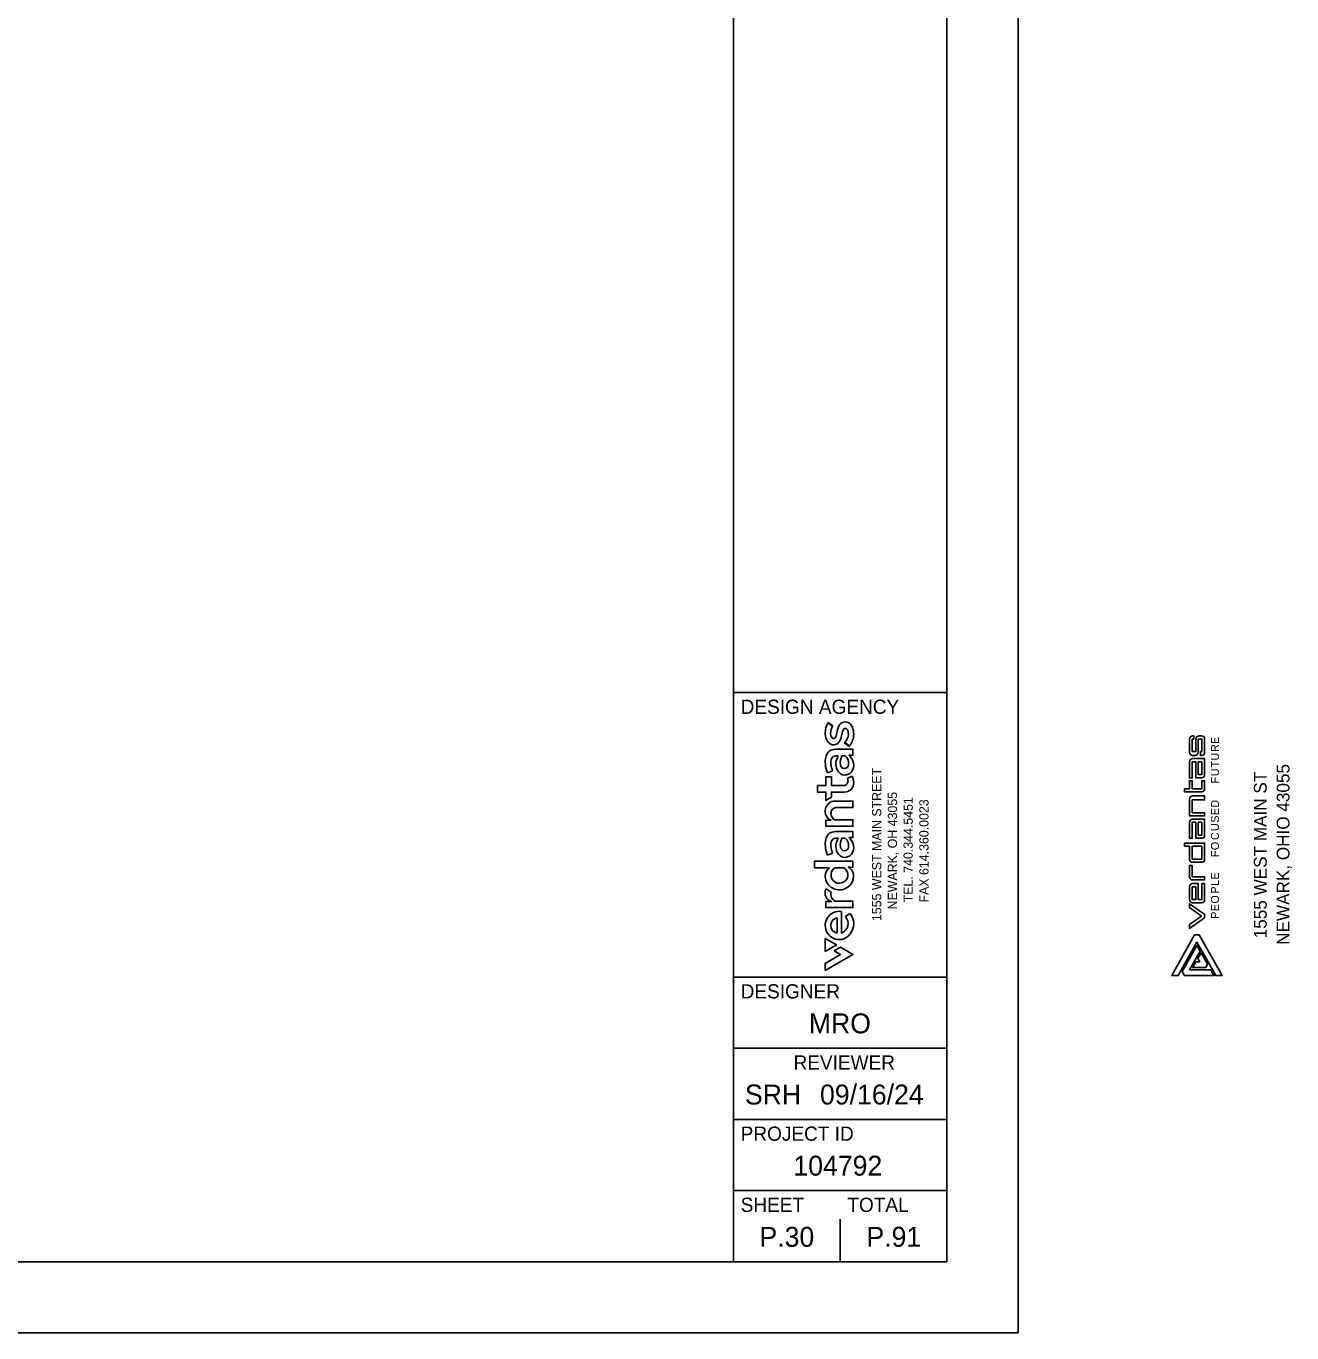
# Model space of a CAD drawing. Extents: x 0 to 35.9, y 0 to 22.
# Drawn here: x 27.03 to 35.93, y 0 to 9.18 of the extents above; entities that cross this region are included whole.
import ezdxf

# ---------------------------------------------------------------- set-up
doc = ezdxf.new("R2010")
doc.units = 0
for name, color, linetype in [('CS-ANNO-TTLB-LOGO', 7, 'Continuous'), ('Default', 7, 'Continuous'), ('SH_Border', 7, 'Continuous'), ('SH_Cut_Line', 7, 'Continuous'), ('SH_Data', 7, 'Continuous'), ('SH_Text', 7, 'Continuous')]:
    doc.layers.add(name, color=color, linetype=linetype)

msp = doc.modelspace()

# ---------------------------------------------------------------- linework, layer by layer
at = {"layer": 'CS-ANNO-TTLB-LOGO'}
for p, q in [((35.205, 4.1732), (35.205, 4.0804)), ((35.2359, 4.1957), (35.2275, 4.1957)), ((35.2893, 4.1957), (35.2725, 4.1957)), ((35.3118, 4.0804), (35.3118, 4.1732)), ((35.2275, 4.0579), (35.2443, 4.0579)), ((35.205, 3.9004), (35.205, 4.0129)), ((35.205, 3.4756), (35.205, 3.5881)), ((35.2275, 3.3069), (35.2893, 3.3069)), ((35.205, 3.1353), (35.205, 3.0453)), ((35.3118, 3.0453), (35.3118, 3.1578)), ((35.2275, 3.0228), (35.2893, 3.0228))]:
    msp.add_line(p, q, dxfattribs=at)
for points in [[(35.25, 4.1732), (35.25, 4.086), (35.2247, 4.086), (35.2247, 4.1732), (35.2359, 4.1732), (35.2359, 4.1957)], [(35.2668, 4.0804), (35.2668, 4.1732), (35.2922, 4.1732), (35.2922, 4.086), (35.2837, 4.086), (35.2837, 4.0579), (35.2893, 4.0579)], [(35.2893, 3.9004), (35.25, 3.9004), (35.25, 4.0129), (35.2247, 4.0129), (35.2247, 3.9004), (35.205, 3.9004)], [(35.2275, 4.0354), (35.3118, 4.0354), (35.3118, 3.9229)], [(35.1703, 3.8244), (35.205, 3.8244), (35.205, 3.8806), (35.2247, 3.8806), (35.2247, 3.8244), (35.2922, 3.8244), (35.2922, 3.8806), (35.3118, 3.8806), (35.3118, 3.8244)], [(35.2893, 3.8019), (35.1703, 3.8019), (35.1703, 3.8244)], [(35.3118, 3.7456), (35.3118, 3.7737), (35.2275, 3.7737)], [(35.205, 3.7512), (35.205, 3.6331), (35.3118, 3.6331), (35.3118, 3.6556), (35.2247, 3.6556), (35.2247, 3.7456), (35.3118, 3.7456)], [(35.2893, 3.4756), (35.25, 3.4756), (35.25, 3.5881), (35.2247, 3.5881), (35.2247, 3.4756), (35.205, 3.4756)], [(35.2275, 3.6106), (35.3118, 3.6106), (35.3118, 3.4981)], [(35.1703, 3.4419), (35.1703, 3.4194), (35.205, 3.4194), (35.205, 3.3294)], [(35.3118, 3.3294), (35.3118, 3.4419), (35.1703, 3.4419)], [(35.3118, 3.2056), (35.2247, 3.2056), (35.2247, 3.2844), (35.205, 3.2844), (35.205, 3.2056)], [(35.2275, 3.1831), (35.3118, 3.1831), (35.3118, 3.2056)], [(35.3118, 3.1578), (35.2922, 3.1578), (35.2922, 3.0453), (35.2668, 3.0453), (35.2668, 3.1578), (35.2275, 3.1578)]]:
    msp.add_lwpolyline(points, dxfattribs=at)
for points in [[(35.2668, 4.0129), (35.2922, 4.0129), (35.2922, 3.9229), (35.2668, 3.9229)], [(35.2668, 3.5881), (35.2922, 3.5881), (35.2922, 3.4981), (35.2668, 3.4981)], [(35.2247, 3.4194), (35.2247, 3.3294), (35.2922, 3.3294), (35.2922, 3.4194)], [(35.25, 3.1353), (35.2247, 3.1353), (35.2247, 3.0453), (35.25, 3.0453)], [(35.2894, 2.929), (35.205, 2.8699), (35.205, 2.8424), (35.3118, 2.9173), (35.3123, 2.9405), (35.2054, 3.0153), (35.205, 2.9882)]]:
    msp.add_lwpolyline(points, close=True, dxfattribs=at)
for centre, start, end in [((35.2275, 4.1732), 90, 180), ((35.2725, 4.1732), 90, 180), ((35.2893, 4.1732), 360, 90), ((35.2275, 4.0804), 180, 270), ((35.2443, 4.0804), 270, 0), ((35.2893, 4.0804), 270, 0), ((35.2275, 4.0129), 90, 180), ((35.2893, 3.9229), 270, 360), ((35.2275, 3.7512), 90, 180), ((35.2893, 3.8244), 270, 360), ((35.2275, 3.5881), 90, 180), ((35.2893, 3.4981), 270, 360), ((35.2275, 3.3294), 180, 270), ((35.2893, 3.3294), 270, 0), ((35.2275, 3.2056), 180, 270), ((35.2275, 3.1353), 90, 180), ((35.2275, 3.0453), 180, 270), ((35.2893, 3.0453), 270, 0)]:
    msp.add_arc(centre, 0.0225, start, end, dxfattribs=at)
at = {"layer": 'Default'}
for p, q in [((35.205, 4.1732), (35.205, 4.0804)), ((35.2893, 4.1957), (35.2725, 4.1957)), ((35.3118, 4.0804), (35.3118, 4.1732)), ((35.2275, 4.0579), (35.2443, 4.0579)), ((35.2275, 3.3069), (35.2893, 3.3069)), ((35.205, 3.1353), (35.205, 3.0453)), ((35.2275, 3.0228), (35.2893, 3.0228)), ((35.1545, 2.5389), (35.2578, 2.7221)), ((35.2804, 2.682), (35.2062, 2.5505)), ((35.2578, 2.7221), (35.2804, 2.682)), ((35.1701, 2.5112), (35.1545, 2.5389)), ((35.3768, 2.5112), (35.1701, 2.5112)), ((35.2062, 2.5505), (35.3545, 2.5505)), ((35.3545, 2.5505), (35.3768, 2.5112))]:
    msp.add_line(p, q, dxfattribs=at)
for points in [[(35.25, 4.1732), (35.25, 4.086), (35.2247, 4.086), (35.2247, 4.1732), (35.2359, 4.1732), (35.2359, 4.1957), (35.2275, 4.1957)], [(35.2668, 4.0804), (35.2668, 4.1732), (35.2922, 4.1732), (35.2922, 4.086), (35.2837, 4.086), (35.2837, 4.0579), (35.2893, 4.0579)], [(35.205, 4.0129), (35.205, 3.9004), (35.2247, 3.9004), (35.2247, 4.0129), (35.25, 4.0129), (35.25, 3.9004), (35.2893, 3.9004)], [(35.3118, 3.9229), (35.3118, 4.0354), (35.2275, 4.0354)], [(35.3118, 3.8244), (35.3118, 3.8806), (35.2922, 3.8806), (35.2922, 3.8244), (35.2247, 3.8244), (35.2247, 3.8806), (35.205, 3.8806), (35.205, 3.8244), (35.1703, 3.8244), (35.1703, 3.8019), (35.2893, 3.8019)], [(35.205, 3.7512), (35.205, 3.6331), (35.3118, 3.6331), (35.3118, 3.6556), (35.2247, 3.6556), (35.2247, 3.7456), (35.3118, 3.7456), (35.3118, 3.7737), (35.2275, 3.7737)], [(35.205, 3.5881), (35.205, 3.4756), (35.2247, 3.4756), (35.2247, 3.5881), (35.25, 3.5881), (35.25, 3.4756), (35.2893, 3.4756)], [(35.3118, 3.4981), (35.3118, 3.6106), (35.2275, 3.6106)], [(35.3118, 3.3294), (35.3118, 3.4419), (35.1703, 3.4419), (35.1703, 3.4194), (35.205, 3.4194), (35.205, 3.3294)], [(35.2275, 3.1831), (35.3118, 3.1831), (35.3118, 3.2056), (35.2247, 3.2056), (35.2247, 3.2844), (35.205, 3.2844), (35.205, 3.2056)], [(35.3118, 3.0453), (35.3118, 3.1578), (35.2922, 3.1578), (35.2922, 3.0453), (35.2668, 3.0453), (35.2668, 3.1578), (35.2275, 3.1578)]]:
    msp.add_lwpolyline(points, dxfattribs=at)
for points in [[(35.2922, 4.0129), (35.2922, 3.9229), (35.2668, 3.9229), (35.2668, 4.0129)], [(35.2922, 3.5881), (35.2922, 3.4981), (35.2668, 3.4981), (35.2668, 3.5881)], [(35.2247, 3.4194), (35.2922, 3.4194), (35.2922, 3.3294), (35.2247, 3.3294)], [(35.25, 3.1353), (35.25, 3.0453), (35.2247, 3.0453), (35.2247, 3.1353)], [(35.205, 2.8699), (35.205, 2.8424), (35.3118, 2.9173), (35.3123, 2.9405), (35.2054, 3.0153), (35.205, 2.9882), (35.2894, 2.929)], [(35.2578, 2.745), (35.3897, 2.5112), (35.4349, 2.5112), (35.2739, 2.7965), (35.2417, 2.7965), (35.0807, 2.5112), (35.1259, 2.5112)], [(35.1259, 2.5112), (35.2578, 2.745), (35.3897, 2.5112), (35.4349, 2.5112), (35.2739, 2.7965), (35.2417, 2.7965), (35.0807, 2.5112)], [(35.1545, 2.5389), (35.1701, 2.5112), (35.3768, 2.5112), (35.3545, 2.5505), (35.2062, 2.5505), (35.2804, 2.682), (35.2578, 2.7221)], [(35.2509, 2.6068), (35.2287, 2.5674), (35.3191, 2.5674), (35.3321, 2.5904), (35.2869, 2.6706), (35.2643, 2.6305), (35.2776, 2.6068)], [(35.2509, 2.6068), (35.2776, 2.6068), (35.2643, 2.6305), (35.2869, 2.6706), (35.3321, 2.5904), (35.3191, 2.5674), (35.2287, 2.5674)]]:
    msp.add_lwpolyline(points, close=True, dxfattribs=at)
for centre, start, end in [((35.2275, 4.1732), 90, 180), ((35.2725, 4.1732), 90, 180), ((35.2893, 4.1732), 360, 90), ((35.2275, 4.0804), 180, 270), ((35.2443, 4.0804), 270, 0), ((35.2893, 4.0804), 270, 0), ((35.2275, 4.0129), 90, 180), ((35.2893, 3.9229), 270, 0), ((35.2275, 3.7512), 90, 180), ((35.2893, 3.8244), 270, 0), ((35.2275, 3.5881), 90, 180), ((35.2893, 3.4981), 270, 0), ((35.2275, 3.3294), 180, 270), ((35.2893, 3.3294), 270, 0), ((35.2275, 3.2056), 180, 270), ((35.2275, 3.1353), 90, 180), ((35.2275, 3.0453), 180, 270), ((35.2893, 3.0453), 270, 0)]:
    msp.add_arc(centre, 0.0225, start, end, dxfattribs=at)
at = {"layer": 'SH_Border'}
for p, q in [((32, 0.5), (32, 21.5)), ((32, 4.5), (33.5, 4.5)), ((32, 2.5), (33.5, 2.5)), ((32, 2), (33.5, 2)), ((32, 1.5), (33.5, 1.5)), ((32, 1), (33.5, 1))]:
    msp.add_line(p, q, dxfattribs=at)
msp.add_lwpolyline([(1.5, 21.5), (33.5, 21.5), (33.5, 0.5), (1.5, 0.5)], close=True, dxfattribs=at)
at = {"layer": 'SH_Cut_Line'}
msp.add_lwpolyline([(0, 0), (34, 0), (34, 22), (0, 22)], close=True, dxfattribs=at)
at = {"layer": 'SH_Data'}
for p, q in [((32.75, 3.5), (32.75, 3.5)), ((32.75, 0.5), (32.75, 0.8)), ((32.375, 0.675), (32.375, 0.675))]:
    msp.add_line(p, q, dxfattribs=at)
at = {"layer": 'SH_Text'}
for p, q in [((32.6964, 4.2637), (32.6653, 4.2873)), ((32.7308, 4.2379), (32.724, 4.2068)), ((32.76, 4.1961), (32.7643, 4.216)), ((32.7826, 4.1481), (32.8152, 4.1243)), ((32.7199, 4.0556), (32.736, 4.0556)), ((32.7614, 4.0556), (32.7845, 4.0556)), ((32.6562, 3.9477), (32.6609, 3.9357)), ((32.8336, 3.912), (32.7984, 3.8957)), ((32.7199, 3.4771), (32.736, 3.4771)), ((32.7614, 3.4771), (32.7845, 3.4771)), ((32.6562, 3.3692), (32.6609, 3.3572)), ((32.7144, 3.2688), (32.7748, 3.2688)), ((32.6872, 3.0976), (32.6502, 3.1199)), ((32.7595, 2.8089), (32.7595, 2.9619)), ((32.819, 2.9473), (32.7867, 2.9251)), ((32.7293, 2.917), (32.7293, 2.8098))]:
    msp.add_line(p, q, dxfattribs=at)
for points in [[(32.698, 4.2662), (32.6662, 4.2886), (32.6653, 4.2873)], [(32.6964, 4.2637), (32.698, 4.2662)], [(32.7308, 4.2379), (32.724, 4.2068)], [(32.76, 4.1961), (32.7643, 4.216)], [(32.7826, 4.1481), (32.7803, 4.1457), (32.8118, 4.1207), (32.8152, 4.1243)], [(32.8097, 4.0594), (32.8398, 4.0594), (32.8398, 4.1011), (32.7147, 4.1011)], [(32.8097, 4.0594), (32.8398, 4.0594), (32.8398, 4.1011), (32.7147, 4.1011)], [(32.7199, 4.0556), (32.736, 4.0556)], [(32.7845, 4.0556), (32.7614, 4.0556)], [(32.6609, 3.9357), (32.6966, 3.9502), (32.6928, 3.9595)], [(32.6609, 3.9357), (32.6966, 3.9502), (32.6928, 3.9595)], [(32.7701, 3.8462), (32.6883, 3.8462), (32.6883, 3.9073), (32.6494, 3.9073), (32.6494, 3.8462), (32.591, 3.8462), (32.591, 3.8008), (32.6494, 3.8008), (32.6494, 3.7411), (32.6883, 3.7645), (32.6883, 3.8008), (32.7782, 3.8008)], [(32.7701, 3.8462), (32.6883, 3.8462), (32.6883, 3.9073), (32.6494, 3.9073), (32.6494, 3.8462), (32.591, 3.8462), (32.591, 3.8008), (32.6494, 3.8008), (32.6494, 3.7411), (32.6883, 3.7645), (32.6883, 3.8008), (32.7782, 3.8008)], [(32.6562, 3.9477), (32.6609, 3.9357)], [(32.8336, 3.912), (32.7984, 3.8957)], [(32.7281, 3.6919), (32.8398, 3.6919), (32.8398, 3.7374), (32.7155, 3.7374)], [(32.7281, 3.6919), (32.8398, 3.6919), (32.8398, 3.7374), (32.7155, 3.7374)], [(32.6867, 3.6025), (32.6494, 3.6025), (32.6494, 3.5604), (32.8398, 3.5604), (32.8398, 3.6059), (32.7125, 3.6059)], [(32.6867, 3.6025), (32.6494, 3.6025), (32.6494, 3.5604), (32.8398, 3.5604), (32.8398, 3.6059), (32.7125, 3.6059)], [(32.8097, 3.481), (32.8398, 3.481), (32.8398, 3.5226), (32.7147, 3.5226)], [(32.8097, 3.481), (32.8398, 3.481), (32.8398, 3.5226), (32.7147, 3.5226)], [(32.7199, 3.4771), (32.736, 3.4771)], [(32.7845, 3.4771), (32.7614, 3.4771)], [(32.6756, 3.2688), (32.5686, 3.2688), (32.5686, 3.3143), (32.8398, 3.3143), (32.8398, 3.2727), (32.8063, 3.2727)], [(32.8063, 3.2727), (32.8398, 3.2727), (32.8398, 3.3143), (32.5686, 3.3143), (32.5686, 3.2688), (32.6756, 3.2688)], [(32.6562, 3.3692), (32.6609, 3.3572)], [(32.6609, 3.3572), (32.6966, 3.3717), (32.6928, 3.381)], [(32.6609, 3.3572), (32.6966, 3.3717), (32.6928, 3.381)], [(32.7144, 3.2688), (32.7748, 3.2688)], [(32.6901, 3.0303), (32.6493, 3.0303), (32.6493, 2.9888), (32.8397, 2.9888), (32.8397, 3.0328), (32.7135, 3.0328)], [(32.6901, 3.0303), (32.6493, 3.0303), (32.6493, 2.9888), (32.8397, 2.9888), (32.8397, 3.0328), (32.7135, 3.0328)], [(32.6872, 3.0976), (32.6502, 3.1199)], [(32.7595, 2.8089), (32.7595, 2.9619)], [(32.819, 2.9473), (32.7867, 2.9251)], [(32.7293, 2.8098), (32.7293, 2.917)], [(32.6443, 2.7721), (32.6443, 2.6812), (32.723, 2.7267), (32.6443, 2.7721)], [(32.7082, 2.6851), (32.7528, 2.6594), (32.6443, 2.5967), (32.6443, 2.5466), (32.8395, 2.6594), (32.7516, 2.7101), (32.7082, 2.6851)]]:
    msp.add_lwpolyline(points, dxfattribs=at)
for points in [[(32.723, 2.7267), (32.6443, 2.6812), (32.6443, 2.7721)], [(32.7082, 2.6851), (32.7528, 2.6594), (32.6443, 2.5967), (32.6443, 2.5466), (32.8395, 2.6594), (32.7516, 2.7101)]]:
    msp.add_lwpolyline(points, close=True, dxfattribs=at)
for centre, radius, start, end in [((32.7757, 4.2163), 0.1313, 147.22328, 179.84204), ((32.7757, 4.2163), 0.1313, 147.22328, 179.84204), ((32.7769, 4.2136), 0.0948, 148.12326, 178.11353), ((32.7769, 4.2136), 0.0948, 148.12326, 178.11353), ((32.8572, 4.2092), 0.1296, 154.04469, 167.21491), ((32.8572, 4.2092), 0.1296, 154.04469, 167.21491), ((32.785, 4.2445), 0.0493, 52.70919, 154.21664), ((32.785, 4.2445), 0.0493, 52.70919, 154.21664), ((32.858, 4.2006), 0.0949, 158.18628, 170.63281), ((32.858, 4.2006), 0.0949, 158.18628, 170.63281), ((32.7857, 4.2312), 0.0165, 26.91646, 163.60196), ((32.7857, 4.2312), 0.0165, 26.91646, 163.60196), ((32.7417, 4.2097), 0.0655, 357.00773, 26.31116), ((32.7417, 4.2097), 0.0655, 357.00773, 26.31116), ((32.7698, 4.2287), 0.0711, 22.82777, 50.71565), ((32.7698, 4.2287), 0.0711, 22.82777, 50.71565), ((32.7252, 4.2097), 0.1196, 359.0192, 22.9257), ((32.7252, 4.2097), 0.1196, 359.0192, 22.9257), ((32.7583, 4.2147), 0.1139, 179.01095, 203.55998), ((32.7583, 4.2147), 0.1139, 179.01095, 203.55998), ((32.7154, 4.1957), 0.067, 203.36923, 237.807), ((32.7154, 4.1957), 0.067, 203.36923, 237.807), ((32.7033, 4.1782), 0.0458, 238.94525, 317.68291), ((32.7033, 4.1782), 0.0458, 238.94525, 317.68291), ((32.7523, 4.2156), 0.0702, 179.05393, 195.69208), ((32.7523, 4.2156), 0.0702, 179.05393, 195.69208), ((32.7173, 4.2046), 0.0335, 193.85614, 223.71908), ((32.7173, 4.2046), 0.0335, 193.85614, 223.71908), ((32.7036, 4.1919), 0.0148, 224.78223, 330.43657), ((32.7036, 4.1919), 0.0148, 224.78223, 330.43657), ((32.6435, 4.2219), 0.0819, 332.90022, 349.38313), ((32.6435, 4.2219), 0.0819, 332.90022, 349.38313), ((32.6564, 4.2149), 0.1053, 320.12588, 349.70225), ((32.6564, 4.2149), 0.1053, 320.12588, 349.70225), ((32.714, 4.2112), 0.0932, 317.36304, 356.92436), ((32.714, 4.2112), 0.0932, 317.36304, 356.92436), ((32.7153, 4.2066), 0.1295, 320.51657, 0.43409), ((32.7153, 4.2066), 0.1295, 320.51657, 0.43409), ((32.7726, 4.0139), 0.1283, 160.81276, 180.93166), ((32.7726, 4.0139), 0.1283, 160.81276, 180.93166), ((32.7126, 4.0372), 0.0639, 88.07599, 162.86424), ((32.7126, 4.0372), 0.0639, 88.07599, 162.86424), ((32.7219, 4.0183), 0.0374, 92.96709, 165.223), ((32.7219, 4.0183), 0.0374, 92.96709, 165.223), ((32.8283, 3.9987), 0.1085, 148.34975, 202.47075), ((32.8283, 3.9987), 0.1085, 148.34975, 202.47075), ((32.8555, 4.0094), 0.1048, 153.83718, 188.87457), ((32.8555, 4.0094), 0.1048, 153.83718, 188.87457), ((32.7456, 4.0052), 0.0637, 348.12474, 52.36783), ((32.7456, 4.0052), 0.0637, 348.12474, 52.36783), ((32.7591, 3.9903), 0.0857, 338.27739, 53.79489), ((32.7591, 3.9903), 0.0857, 338.27739, 53.79489), ((32.843, 4.0151), 0.1986, 180.9467, 199.83537), ((32.843, 4.0151), 0.1986, 180.9467, 199.83537), ((32.7477, 4.0091), 0.0647, 163.25224, 179.99706), ((32.7477, 4.0091), 0.0647, 163.25224, 179.99706), ((32.8344, 4.0135), 0.1516, 181.66161, 200.87137), ((32.8344, 4.0135), 0.1516, 181.66161, 200.87137), ((32.7831, 3.9791), 0.0592, 201.67635, 339.72677), ((32.7831, 3.9791), 0.0592, 201.67635, 339.72677), ((32.78, 3.9944), 0.0281, 182.32704, 355.37776), ((32.78, 3.9944), 0.0281, 182.32704, 355.37776), ((32.7728, 3.8775), 0.0314, 265.06923, 356.35481), ((32.7728, 3.8775), 0.0314, 265.06923, 356.35481), ((32.7806, 3.865), 0.0642, 267.86409, 1.62134), ((32.7806, 3.865), 0.0642, 267.86409, 1.62134), ((32.761, 3.8741), 0.0432, 1.86376, 29.96515), ((32.761, 3.8741), 0.0432, 1.86376, 29.96515), ((32.7509, 3.8675), 0.0939, 359.5424, 28.24947), ((32.7509, 3.8675), 0.0939, 359.5424, 28.24947), ((32.7143, 3.6671), 0.0703, 88.98961, 246.91113), ((32.7143, 3.6671), 0.0703, 88.98961, 246.91113), ((32.7283, 3.6511), 0.0434, 137.30492, 182.96879), ((32.7283, 3.6511), 0.0434, 137.30492, 182.96879), ((32.7258, 3.6487), 0.0433, 86.97388, 132.7421), ((32.7258, 3.6487), 0.0433, 86.97388, 132.7421), ((32.7327, 3.6491), 0.0477, 180.34657, 244.91134), ((32.7327, 3.6491), 0.0477, 180.34657, 244.91134), ((32.7126, 3.4587), 0.0639, 88.07599, 162.86424), ((32.7126, 3.4587), 0.0639, 88.07599, 162.86424), ((32.7726, 3.4354), 0.1283, 160.81276, 180.93166), ((32.7726, 3.4354), 0.1283, 160.81276, 180.93166), ((32.843, 3.4366), 0.1986, 180.9467, 199.83537), ((32.843, 3.4366), 0.1986, 180.9467, 199.83537), ((32.7477, 3.4306), 0.0647, 163.25224, 179.99706), ((32.7477, 3.4306), 0.0647, 163.25224, 179.99706), ((32.8344, 3.435), 0.1516, 181.66161, 200.87137), ((32.8344, 3.435), 0.1516, 181.66161, 200.87137), ((32.7219, 3.4398), 0.0374, 92.96709, 165.223), ((32.7219, 3.4398), 0.0374, 92.96709, 165.223), ((32.8283, 3.4202), 0.1085, 148.34975, 202.47075), ((32.8283, 3.4202), 0.1085, 148.34975, 202.47075), ((32.8555, 3.4309), 0.1048, 153.83718, 188.87457), ((32.8555, 3.4309), 0.1048, 153.83718, 188.87457), ((32.78, 3.4159), 0.0281, 182.32704, 355.37776), ((32.78, 3.4159), 0.0281, 182.32704, 355.37776), ((32.7456, 3.4267), 0.0637, 348.12474, 52.36783), ((32.7456, 3.4267), 0.0637, 348.12474, 52.36783), ((32.7591, 3.4118), 0.0857, 338.27739, 53.79489), ((32.7591, 3.4118), 0.0857, 338.27739, 53.79489), ((32.7831, 3.4006), 0.0592, 201.67635, 339.72677), ((32.7831, 3.4006), 0.0592, 201.67635, 339.72677), ((32.7158, 3.2098), 0.0714, 124.28433, 181.27226), ((32.7158, 3.2098), 0.0714, 124.28433, 181.27226), ((32.7443, 3.2131), 0.1001, 182.77189, 2.9779), ((32.7443, 3.2131), 0.1001, 182.77189, 2.9779), ((32.7446, 3.2189), 0.0595, 176.4529, 5.05495), ((32.7446, 3.2189), 0.0595, 176.4529, 5.05495), ((32.7436, 3.218), 0.0586, 119.90067, 175.57974), ((32.7436, 3.218), 0.0586, 119.90067, 175.57974), ((32.7454, 3.2179), 0.0588, 6.06662, 60.04101), ((32.7454, 3.2179), 0.0588, 6.06662, 60.04101), ((32.7774, 3.2121), 0.0671, 5.30838, 64.52521), ((32.7774, 3.2121), 0.0671, 5.30838, 64.52521), ((32.706, 3.091), 0.0628, 152.6524, 255.29294), ((32.706, 3.091), 0.0628, 152.6524, 255.29294), ((32.7391, 3.0809), 0.0545, 162.13838, 242.04081), ((32.7391, 3.0809), 0.0545, 162.13838, 242.04081), ((32.744, 2.8635), 0.0996, 81.04458, 280.25771), ((32.744, 2.8635), 0.0996, 81.04458, 280.25771), ((32.731, 2.8751), 0.1138, 285.66678, 39.36993), ((32.731, 2.8751), 0.1138, 285.66678, 39.36993), ((32.7376, 2.8634), 0.0543, 98.83779, 261.16221), ((32.7376, 2.8634), 0.0543, 98.83779, 261.16221), ((32.7338, 2.8762), 0.072, 290.92317, 42.73906), ((32.7338, 2.8762), 0.072, 290.92317, 42.73906)]:
    msp.add_arc(centre, radius, start, end, dxfattribs=at)

# ---------------------------------------------------------------- texts
at = {"layer": 'Default'}
for s, p in [('E', (35.4126, 4.1383)), ('R', (35.4126, 4.0825)), ('U', (35.4126, 4.0216)), ('T', (35.4126, 3.973)), ('U', (35.4126, 3.9121)), ('F', (35.4126, 3.8609)), ('D', (35.4126, 3.6906)), ('E', (35.4126, 3.6379)), ('S', (35.4126, 3.5853)), ('C', (35.4126, 3.4637)), ('U', (35.4126, 3.5267)), ('O', (35.4126, 3.3926)), ('F', (35.4126, 3.3436)), ('E', (35.4126, 3.1856)), ('L', (35.4126, 3.1403)), ('P', (35.4126, 3.0875)), ('O', (35.4126, 3.0162)), ('E', (35.4126, 2.9633)), ('P', (35.4126, 2.9105))]:
    msp.add_text(s, height=0.0563, rotation=90, dxfattribs=at).set_placement(p)
at = {"layer": 'SH_Data'}
for s, height, p in [('DESIGN AGENCY', 0.1, (32.05, 4.35)), ('DESIGNER', 0.1, (32.05, 2.35)), ('MRO', 0.14, (32.5292, 2.105)), ('REVIEWER', 0.1, (32.4218, 1.85)), ('SRH', 0.14, (32.08, 1.605)), ('09/16/24', 0.14, (32.6078, 1.605)), ('PROJECT ID', 0.1, (32.05, 1.35)), ('104792', 0.14, (32.4209, 1.105)), ('SHEET', 0.1, (32.05, 0.85)), ('TOTAL', 0.1, (32.8, 0.85)), ('P.30', 0.14, (32.1822, 0.605)), ('P.91', 0.14, (32.9344, 0.605))]:
    msp.add_text(s, height=height, dxfattribs=at).set_placement(p)
at = {"layer": 'SH_Text'}
for s, height, p in [('1555 WEST MAIN STREET', 0.064969, (33.0391, 2.8939)), ('NEWARK, OHIO 43055', 0.09, (35.9083, 2.7268)), ('1555 WEST MAIN ST', 0.09, (35.7483, 2.7729)), ('NEWARK, OH 43055', 0.064969, (33.1496, 2.9758)), ('TEL. 740.344.5451', 0.064969, (33.26, 3.0255)), ('FAX 614.360.0023', 0.064969, (33.3707, 3.0248))]:
    msp.add_text(s, height=height, rotation=90, dxfattribs=at).set_placement(p)

doc.saveas('drawing.dxf')
